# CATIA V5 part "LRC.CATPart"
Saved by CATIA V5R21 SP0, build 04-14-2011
Part number: LRC.SLDPRT
Bounding box of the stored display mesh (mm): x -1.7 to 1.7, y -1.65 to 1.65, z -1.105 to 0.8
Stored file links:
  C:\Users\user\Desktop\CATIA文件\0-最新文件(2025.3月之前的慎用)\LRC\LRC.CATPart
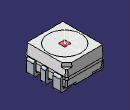
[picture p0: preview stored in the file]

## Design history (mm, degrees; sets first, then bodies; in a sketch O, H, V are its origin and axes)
AxisSystem1: origin (0, 0, 0.8), X (0, 1, 0), Y (-1, 0, 0), Z (0, 0, 1)
Set1
  DatumSurface1 to DatumSurface139
  Circle1: stored without definition
  Circle2: stored without definition
  DatumCurve1 to DatumCurve5
  Line1 to Line5: stored without definition
  DatumCurve6 to DatumCurve12
  Line6: stored without definition
  Circle3 to Circle8: stored without definition
  Line7: stored without definition
  Circle9: stored without definition
  Line8: stored without definition
  Circle10: stored without definition
  Line9: stored without definition
  Circle11: stored without definition
  Line10: stored without definition
  Circle12: stored without definition
  Line11 to Line13: stored without definition
  Circle13: stored without definition
  Line14: stored without definition
  Circle14: stored without definition
  Line15 to Line23: stored without definition
  Circle15: stored without definition
  Line24: stored without definition
  Circle16: stored without definition
  Line25 to Line27: stored without definition
  Circle17: stored without definition
  Line28: stored without definition
  Circle18: stored without definition
  Line29 to Line40: stored without definition
  Circle19: stored without definition
  Line41: stored without definition
  Circle20: stored without definition
  Line42 to Line44: stored without definition
  Circle21: stored without definition
  Line45: stored without definition
  Circle22: stored without definition
  Line46 to Line54: stored without definition
  Circle23: stored without definition
  Line55: stored without definition
  Circle24: stored without definition
  Line56 to Line58: stored without definition
  Circle25: stored without definition
  Line59: stored without definition
  Circle26: stored without definition
  Line60 to Line65: stored without definition
  Circle27 to Circle29: stored without definition
  Line66: stored without definition
  Circle30: stored without definition
  Line67: stored without definition
  Circle31: stored without definition
  Line68: stored without definition
  Circle32: stored without definition
  Line69: stored without definition
  Circle33 to Circle38: stored without definition
  Line70: stored without definition
  Line71: stored without definition
  Circle39: stored without definition
  Circle40: stored without definition
  Line72 to Line78: stored without definition
  DatumCurve13
  DatumCurve14
  Line79: stored without definition
  Line80: stored without definition
  Circle41: stored without definition
  Line81: stored without definition
  DatumCurve15
  Line82: stored without definition
  Line83: stored without definition
  DatumCurve16
  Line84: stored without definition
  Circle42: stored without definition
  Line85: stored without definition
  DatumCurve17
  Line86: stored without definition
  DatumCurve18
  Line87 to Line89: stored without definition
  DatumCurve19
  DatumCurve20
  Line90: stored without definition
  Circle43: stored without definition
  Line91: stored without definition
  Circle44: stored without definition
  Circle45: stored without definition
  Line92: stored without definition
  Circle46 to Circle49: stored without definition
  Line93: stored without definition
  Circle50: stored without definition
  Line94 to Line99: stored without definition
  DatumCurve21
  Line100: stored without definition
  Circle51: stored without definition
  Line101: stored without definition
  Line102: stored without definition
  DatumCurve22
  Line103 to Line111: stored without definition
  DatumCurve23
  Line112: stored without definition
  DatumCurve24
  Line113: stored without definition
  Circle52: stored without definition
  DatumCurve25
  Line114 to Line116: stored without definition
  Circle53: stored without definition
  Line117 to Line124: stored without definition
  DatumCurve26
  Line125: stored without definition
  DatumCurve27 to DatumCurve29
  Circle54: stored without definition
  Line126: stored without definition
  Circle55: stored without definition
  Line127 to Line129: stored without definition
  DatumCurve30
  Line130: stored without definition
  Line131: stored without definition
  DatumCurve31
  Line132 to Line139: stored without definition
  DatumCurve32
  Line140 to Line143: stored without definition
  DatumCurve33
  Line144 to Line169: stored without definition
  Circle56: stored without definition
  Line170: stored without definition
  Circle57: stored without definition
  Line171 to Line173: stored without definition
  Circle58: stored without definition
  Line174: stored without definition
  Circle59: stored without definition
  Line175 to Line183: stored without definition
  Circle60: stored without definition
  Line184: stored without definition
  Circle61: stored without definition
  Line185 to Line187: stored without definition
  Circle62: stored without definition
  Circle63: stored without definition
  Line188: stored without definition
  Circle64: stored without definition
  Circle65: stored without definition
  Line189 to Line191: stored without definition
  Circle66: stored without definition
  Line192: stored without definition
  Circle67: stored without definition
  Line193 to Line201: stored without definition
  Circle68: stored without definition
  Line202: stored without definition
  Circle69: stored without definition
  Line203 to Line205: stored without definition
  Circle70: stored without definition
  Line206: stored without definition
  Circle71: stored without definition
  Line207: stored without definition
  Line208: stored without definition
  Circle72: stored without definition
  Line209: stored without definition
  Circle73: stored without definition
  Line210 to Line212: stored without definition
  Circle74: stored without definition
  Line213: stored without definition
  Circle75: stored without definition
  Line214 to Line216: stored without definition
  Circle76: stored without definition
  Line217 to Line219: stored without definition
  Circle77: stored without definition
  Line220 to Line227: stored without definition
  Circle78: stored without definition
  Line228: stored without definition
  Line229: stored without definition
  Circle79: stored without definition
  Line230: stored without definition
  Circle80: stored without definition
  Line231: stored without definition
  Circle81: stored without definition
  Line232 to Line234: stored without definition
  Circle82: stored without definition
  Line235: stored without definition
  Circle83: stored without definition
  Line236: stored without definition
  Circle84: stored without definition
  Line237 to Line239: stored without definition
  Circle85: stored without definition
  Line240 to Line245: stored without definition
  Circle86: stored without definition
  Line246 to Line248: stored without definition
  Circle87: stored without definition
  Line249: stored without definition
  Line250: stored without definition
  Circle88: stored without definition
  Line251 to Line258: stored without definition
  Point1 "发光中心&几何中心（测试原点）": type Between, FirstPoint vertex [face of DatumSurface139], SecondPoint vertex [face of DatumSurface139], Ratio 0.5
  Point2 "虚拟坐标": (-0.002, 0.026, -0.118), relative to Point1, in AxisSystem1
Body1 (main body)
